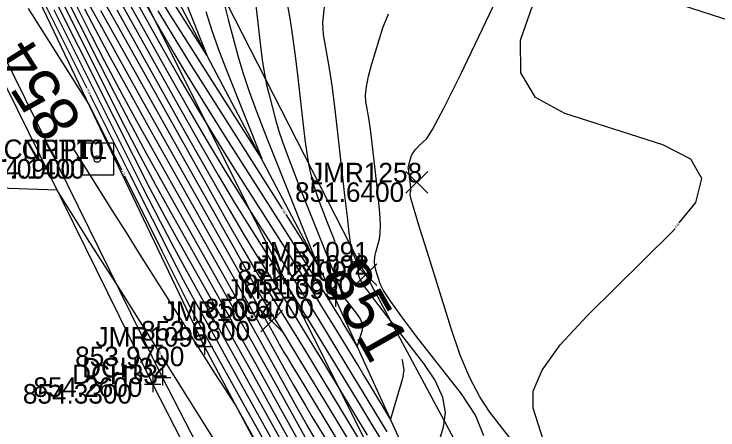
# Model space of a CAD drawing. Extents: x 1654928 to 1810050, y 486881 to 626330.
# Drawn here: x 1801458.38 to 1801501.55, y 489771.84 to 489797.37 of the extents above; entities that cross this region are included whole.
import ezdxf

# ---------------------------------------------------------------- set-up
doc = ezdxf.new("R2010")
doc.units = 0
for name, color, linetype in [('DR_X_Ditch', 7, 'Continuous'), ('DT_X_Contour_Major', 7, 'Continuous'), ('DT_X_Contour_Minor', 7, 'Continuous'), ('PV_X_EOP', 7, 'Continuous'), ('PV_X_Shoulder', 7, 'Continuous'), ('RD_X_Fence', 7, 'Continuous'), ('RW_X_Esmt_SH', 7, 'Continuous'), ('SV_P_Control_Cells_Set', 7, 'Continuous'), ('SV_X_Break_Lines', 7, 'Continuous'), ('SV_X_Control_Cells_Found', 7, 'Continuous'), ('SV_X_Random_Point', 7, 'Continuous'), ('SV_X_Shot_Marker', 7, 'Continuous'), ('SV_X_Text_Elevation', 7, 'Continuous'), ('SV_X_Text_Name', 7, 'Continuous')]:
    doc.layers.add(name, color=color, linetype=linetype)

msp = doc.modelspace()

# ---------------------------------------------------------------- linework, layer by layer
at = {"layer": 'DR_X_Ditch'}
msp.add_lwpolyline([(1801540.062, 489643.432), (1801532.556, 489660.144), (1801517.868, 489690.883), (1801504.345, 489723.544), (1801491.469, 489750.565), (1801478.102, 489779.895), (1801464.666, 489805.356), (1801460.448, 489815.434)], dxfattribs=at)
at = {"layer": 'DT_X_Contour_Major'}
for points in [[(1801511.18, 489796.356), (1801511.157, 489796.211), (1801510.687, 489795.44), (1801509.604, 489795.13), (1801507.907, 489795.282), (1801505.597, 489795.895), (1801498.619, 489798.146), (1801496.431, 489799.099), (1801495.102, 489800.27), (1801494.631, 489801.658), (1801495.019, 489803.265), (1801497.199, 489807.839)], [(1801482.153, 489776.192), (1801482.179, 489776.131), (1801482.279, 489775.543), (1801482.207, 489774.992), (1801481.469, 489772.507), (1801480.075, 489774.807), (1801479.77, 489775.309), (1801479.454, 489775.83), (1801479.127, 489776.37), (1801477.871, 489778.441), (1801477.427, 489779.164), (1801476.781, 489780.197), (1801475.934, 489781.541), (1801474.886, 489783.196), (1801471.824, 489788.021), (1801470.69, 489789.837), (1801469.582, 489791.664), (1801468.501, 489793.504), (1801467.447, 489795.356), (1801464.672, 489800.31)], [(1801492.367, 489742.188), (1801490.238, 489746.399), (1801489.524, 489747.806), (1801488.978, 489748.87), (1801488.601, 489749.591), (1801488.391, 489749.969), (1801484.363, 489756.609), (1801481.276, 489761.695), (1801480.136, 489763.593), (1801479.031, 489765.475), (1801477.96, 489767.339), (1801476.925, 489769.186), (1801474.21, 489774.088), (1801473.207, 489775.896), (1801472.235, 489777.643), (1801471.293, 489779.329), (1801470.381, 489780.954), (1801467.99, 489785.207), (1801467.073, 489786.869), (1801466.115, 489788.665), (1801465.114, 489790.594), (1801464.073, 489792.657), (1801461.24, 489798.336)], [(1801475.156, 489797.899), (1801475.311, 489796.983), (1801475.459, 489795.997), (1801475.6, 489794.941), (1801475.735, 489793.817), (1801476.086, 489790.725), (1801476.212, 489789.67), (1801476.326, 489788.824), (1801476.429, 489788.187), (1801476.52, 489787.758), (1801476.749, 489786.893), (1801476.861, 489786.515), (1801477.027, 489786.03), (1801477.247, 489785.437), (1801477.521, 489784.737), (1801478.05, 489783.412)], [(1801463.673, 489797.598), (1801464.857, 489795.484), (1801468.386, 489789.206), (1801469.596, 489787.053), (1801470.581, 489785.3), (1801471.339, 489783.949), (1801471.872, 489782.999), (1801472.991, 489781.001), (1801473.369, 489780.329), (1801473.663, 489779.81), (1801473.874, 489779.445), (1801474.001, 489779.234), (1801474.227, 489778.877), (1801474.475, 489778.474), (1801475.048, 489777.532), (1801475.947, 489776.053), (1801477.171, 489774.035), (1801480.869, 489767.936), (1801482.228, 489765.694), (1801483.532, 489763.544), (1801484.781, 489761.485), (1801485.974, 489759.517), (1801487.345, 489757.255)], [(1801487.169, 489745.96), (1801486.321, 489747.603), (1801485.711, 489748.755), (1801485.34, 489749.416), (1801484.668, 489750.523), (1801484.219, 489751.3), (1801483.375, 489752.798), (1801482.136, 489755.02), (1801480.504, 489757.963), (1801471.964, 489773.384), (1801471.097, 489774.705), (1801470.917, 489774.981), (1801470.593, 489775.488), (1801470.447, 489775.718), (1801470.076, 489776.314), (1801469.855, 489776.667), (1801469.471, 489777.279), (1801468.213, 489779.28), (1801466.1, 489782.638), (1801465.27, 489783.958), (1801464.364, 489785.399), (1801463.382, 489786.961), (1801461.991, 489789.174)]]:
    msp.add_lwpolyline(points, dxfattribs=at)
at = {"layer": 'DT_X_Contour_Minor'}
for points in [[(1801489.278, 489770.727), (1801487.566, 489772.927), (1801486.936, 489773.868), (1801486.33, 489775.039), (1801485.747, 489776.441), (1801485.189, 489778.073), (1801483.73, 489782.734), (1801483.253, 489784.269), (1801482.917, 489785.38), (1801482.72, 489786.066), (1801482.664, 489786.327), (1801482.7, 489786.457), (1801482.71, 489786.519), (1801482.712, 489786.609), (1801482.706, 489786.726), (1801482.692, 489786.87), (1801482.644, 489787.292), (1801482.627, 489787.437), (1801482.612, 489787.557), (1801482.599, 489787.65), (1801482.588, 489787.718), (1801482.562, 489787.865), (1801482.558, 489787.931), (1801482.568, 489788.017), (1801482.59, 489788.124), (1801482.625, 489788.252), (1801482.735, 489788.622), (1801482.794, 489788.765), (1801482.891, 489788.918), (1801483.023, 489789.082), (1801483.193, 489789.255), (1801483.692, 489789.729), (1801484.047, 489790.283), (1801484.734, 489791.59), (1801485.754, 489793.65), (1801487.107, 489796.463), (1801491.16, 489804.967)], [(1801473.171, 489798.214), (1801473.277, 489797.362), (1801473.521, 489795.207), (1801473.621, 489794.426), (1801473.737, 489793.698), (1801473.87, 489793.023), (1801474.019, 489792.402), (1801474.437, 489790.816), (1801474.643, 489790.123), (1801474.948, 489789.234), (1801475.352, 489788.147), (1801475.854, 489786.864), (1801477.806, 489781.967), (1801478.152, 489781.09), (1801478.361, 489780.549), (1801478.434, 489780.344), (1801478.444, 489780.247), (1801478.473, 489780.181), (1801478.554, 489780.057), (1801478.686, 489779.876), (1801478.869, 489779.636), (1801479.426, 489778.92), (1801479.601, 489778.659), (1801479.708, 489778.413), (1801479.748, 489778.181), (1801479.719, 489777.964), (1801479.429, 489776.985), (1801478.879, 489777.891), (1801478.506, 489778.507), (1801478.373, 489778.727), (1801478.011, 489779.323), (1801477.722, 489779.786), (1801477.127, 489780.73), (1801475.018, 489784.059), (1801471.389, 489789.779), (1801470.091, 489791.846), (1801468.92, 489793.76), (1801467.874, 489795.52), (1801466.955, 489797.126), (1801464.671, 489801.203)], [(1801492.762, 489740.113), (1801488.304, 489748.928), (1801488.056, 489749.367), (1801487.533, 489750.251), (1801486.734, 489751.581), (1801485.66, 489753.356), (1801482.427, 489758.683), (1801481.211, 489760.71), (1801479.988, 489762.798), (1801478.759, 489764.946), (1801477.523, 489767.154), (1801474.218, 489773.122), (1801473.044, 489775.238), (1801472.003, 489777.112), (1801471.093, 489778.742), (1801470.316, 489780.13), (1801468.418, 489783.506), (1801467.641, 489784.923), (1801466.734, 489786.64), (1801465.697, 489788.659), (1801464.53, 489790.979), (1801460.148, 489799.762)], [(1801492.015, 489745.473), (1801490.721, 489748.032), (1801490.228, 489748.984), (1801489.722, 489749.919), (1801489.202, 489750.836), (1801488.668, 489751.737), (1801481.987, 489762.756), (1801479.933, 489766.141), (1801478.189, 489769.015), (1801477.544, 489770.088), (1801476.919, 489771.151), (1801476.314, 489772.205), (1801475.729, 489773.249), (1801474.195, 489776.02), (1801473.533, 489777.211), (1801472.699, 489778.705), (1801471.691, 489780.502), (1801467.135, 489788.61), (1801465.937, 489790.762), (1801464.875, 489792.713), (1801463.948, 489794.463), (1801463.158, 489796.012), (1801461.231, 489799.874)], [(1801492.191, 489743.83), (1801490.479, 489747.216), (1801489.876, 489748.395), (1801489.35, 489749.394), (1801488.901, 489750.214), (1801488.53, 489750.853), (1801487.294, 489752.892), (1801482.148, 489761.375), (1801479.732, 489765.355), (1801478.84, 489766.841), (1801477.975, 489768.313), (1801477.137, 489769.772), (1801476.327, 489771.217), (1801474.202, 489775.054), (1801473.37, 489776.553), (1801472.467, 489778.174), (1801471.492, 489779.916), (1801467.563, 489786.909), (1801466.505, 489788.816), (1801465.495, 489790.689), (1801464.531, 489792.529), (1801463.615, 489794.334), (1801461.235, 489799.105)], [(1801481.27, 489771.723), (1801479.748, 489774.233), (1801479.205, 489775.13), (1801477.731, 489777.56), (1801477.131, 489778.542), (1801476.434, 489779.664), (1801475.642, 489780.928), (1801474.755, 489782.332), (1801472.26, 489786.264), (1801471.288, 489787.827), (1801470.244, 489789.569), (1801469.128, 489791.488), (1801467.939, 489793.586), (1801464.673, 489799.417)], [(1801468.834, 489798.299), (1801470.208, 489794.854), (1801467.323, 489799.402)], [(1801462.866, 489792.795), (1801461.252, 489796.03), (1801459.873, 489798.793)], [(1801462.782, 489798.333), (1801463.635, 489796.762), (1801464.801, 489794.655), (1801466.28, 489792.013), (1801473.162, 489779.767), (1801473.859, 489778.525), (1801474.179, 489777.952), (1801474.533, 489777.312), (1801474.668, 489777.072), (1801474.808, 489776.828), (1801474.952, 489776.583), (1801475.101, 489776.335), (1801475.504, 489775.672), (1801475.798, 489775.186), (1801478.407, 489770.885)], [(1801463.78, 489798.337), (1801464.797, 489796.522), (1801470.032, 489787.175), (1801471.355, 489784.822), (1801472.384, 489783.007), (1801473.121, 489781.73), (1801473.565, 489780.992), (1801474.359, 489779.741), (1801474.767, 489779.087), (1801475.395, 489778.065), (1801476.243, 489776.675), (1801477.311, 489774.916), (1801480.453, 489769.734)], [(1801464.674, 489798.523), (1801468.431, 489791.816), (1801469.754, 489789.473), (1801470.906, 489787.473), (1801471.886, 489785.818), (1801472.695, 489784.506), (1801474.623, 489781.468), (1801475.351, 489780.314), (1801476.088, 489779.131), (1801476.835, 489777.92), (1801477.591, 489776.679), (1801479.621, 489773.331), (1801480.37, 489772.096), (1801481.093, 489770.903)], [(1801470.135, 489797.521), (1801470.5, 489796.367), (1801470.908, 489795.2), (1801471.36, 489794.021), (1801473.567, 489788.488), (1801468.933, 489795.793), (1801468.003, 489797.271), (1801467.199, 489798.576)], [(1801499.179, 489784.546), (1801500.188, 489785.805), (1801500.564, 489787.284), (1801499.89, 489788.462), (1801498.165, 489789.339), (1801492.163, 489791.274), (1801490.36, 489792.258), (1801489.451, 489793.757), (1801489.437, 489795.771), (1801490.318, 489798.3)], [(1801471.311, 489797.86), (1801471.517, 489797.046), (1801472.126, 489794.739), (1801472.407, 489793.779), (1801472.794, 489792.626), (1801473.287, 489791.281), (1801473.885, 489789.744), (1801476.927, 489782.123), (1801475.06, 489785.065)], [(1801477.408, 489797.793), (1801477.305, 489796.843), (1801477.343, 489796.122), (1801477.633, 489794.505), (1801477.75, 489793.786), (1801477.882, 489792.841), (1801478.03, 489791.669), (1801478.193, 489790.272), (1801478.651, 489786.243), (1801478.802, 489784.915), (1801478.915, 489783.95), (1801478.988, 489783.35), (1801479.022, 489783.114), (1801479.06, 489782.97), (1801479.079, 489782.907), (1801479.107, 489782.826), (1801479.143, 489782.727), (1801479.189, 489782.611), (1801479.323, 489782.276), (1801479.368, 489782.147), (1801479.405, 489782.013), (1801479.434, 489781.872), (1801479.453, 489781.725), (1801479.494, 489781.327), (1801479.614, 489781.059), (1801479.943, 489780.555), (1801480.481, 489779.815), (1801481.228, 489778.838), (1801483.5, 489775.919), (1801484.213, 489774.855), (1801484.65, 489773.85), (1801484.811, 489772.905), (1801484.695, 489772.02), (1801483.51, 489768.029)], [(1801467.18, 489776.791), (1801467.009, 489777.063), (1801464.656, 489780.803), (1801463.754, 489782.209), (1801463.541, 489782.543), (1801463.288, 489782.942), (1801462.995, 489783.407), (1801462.662, 489783.936), (1801461.017, 489786.56), (1801458.059, 489786.668), (1801457.409, 489786.828), (1801456.726, 489787.262), (1801456.01, 489787.969), (1801455.261, 489788.95), (1801453.219, 489791.931), (1801452.443, 489792.987), (1801451.645, 489793.918), (1801450.825, 489794.725), (1801449.983, 489795.408), (1801447.709, 489797.063), (1801446.866, 489797.696)], [(1801464.981, 489787.794), (1801462.976, 489791.812), (1801459.274, 489797.704)], [(1801489.315, 489745.633), (1801488.292, 489747.652), (1801487.835, 489748.515), (1801487.23, 489749.589), (1801486.479, 489750.874), (1801485.58, 489752.371), (1801482.987, 489756.643), (1801481.953, 489758.374), (1801480.798, 489760.365), (1801479.52, 489762.614), (1801478.121, 489765.122), (1801474.226, 489772.156), (1801472.882, 489774.581), (1801471.771, 489776.581), (1801470.894, 489778.156), (1801470.251, 489779.305), (1801468.846, 489781.805), (1801468.21, 489782.976), (1801467.354, 489784.616), (1801466.28, 489786.725), (1801464.987, 489789.302), (1801461.248, 489796.798), (1801460.838, 489797.619)], [(1801462.701, 489797.69), (1801463.365, 489796.398), (1801464.255, 489794.738), (1801465.369, 489792.709), (1801466.707, 489790.312), (1801470.577, 489783.428), (1801471.891, 489781.089), (1801473.696, 489777.868), (1801474.187, 489776.986), (1801475.131, 489775.281), (1801475.491, 489774.638), (1801475.864, 489773.99), (1801476.248, 489773.336), (1801476.645, 489772.675), (1801477.718, 489770.906)], [(1801464.675, 489797.63), (1801468.923, 489790.046), (1801470.381, 489787.457), (1801471.568, 489785.378), (1801472.484, 489783.808), (1801473.13, 489782.749), (1801474.491, 489780.604), (1801475.059, 489779.701), (1801475.741, 489778.598), (1801476.539, 489777.297), (1801477.451, 489775.797), (1801480.037, 489771.533)], [(1801474.835, 489785.419), (1801470.543, 489792.184), (1801469.262, 489794.22), (1801468.155, 489796.018), (1801467.222, 489797.576)], [(1801487.192, 489771.477), (1801486.679, 489772.747), (1801485.821, 489774.054), (1801483.071, 489777.587), (1801482.158, 489778.783), (1801481.479, 489779.72), (1801481.035, 489780.399), (1801480.827, 489780.82), (1801480.584, 489781.597), (1801480.514, 489781.888), (1801480.488, 489782.18), (1801480.505, 489782.472), (1801480.565, 489782.764), (1801480.783, 489783.543), (1801480.841, 489783.917), (1801480.852, 489784.455), (1801480.816, 489785.158), (1801480.732, 489786.024), (1801480.444, 489788.553), (1801480.343, 489789.425), (1801480.253, 489790.142), (1801480.176, 489790.704), (1801480.111, 489791.112), (1801479.952, 489791.994), (1801479.932, 489792.387), (1801479.988, 489792.905), (1801480.12, 489793.549), (1801480.33, 489794.317), (1801480.992, 489796.533), (1801481.349, 489797.394)], [(1801490.034, 489742.915), (1801488.28, 489746.377), (1801487.613, 489747.663), (1801486.927, 489748.927), (1801486.223, 489750.168), (1801485.5, 489751.386), (1801483.547, 489754.603), (1801482.696, 489756.038), (1801481.608, 489757.931), (1801480.282, 489760.282), (1801478.719, 489763.09), (1801474.233, 489771.19), (1801472.719, 489773.923), (1801471.539, 489776.05), (1801470.695, 489777.569), (1801470.185, 489778.481), (1801469.273, 489780.103), (1801468.778, 489781.03), (1801467.974, 489782.592), (1801466.863, 489784.79), (1801465.445, 489787.624), (1801463.053, 489792.419)], [(1801488.268, 489745.101), (1801487.391, 489746.811), (1801486.624, 489748.265), (1801485.967, 489749.461), (1801485.42, 489750.401), (1801484.108, 489752.563), (1801483.439, 489753.702), (1801482.418, 489755.498), (1801481.044, 489757.95), (1801479.317, 489761.059), (1801474.241, 489770.224), (1801472.556, 489773.266), (1801471.307, 489775.519), (1801470.496, 489776.982), (1801470.12, 489777.656), (1801469.701, 489778.402), (1801469.444, 489778.887), (1801468.985, 489779.785), (1801468.325, 489781.095), (1801467.464, 489782.816), (1801465.168, 489787.418)], [(1801490.984, 489770.746), (1801490.221, 489773.183), (1801490.215, 489774.225), (1801490.768, 489775.52), (1801491.881, 489777.07), (1801493.554, 489778.874), (1801498.761, 489784.024), (1801498.916, 489784.218)], [(1801486.948, 489745.108), (1801486.018, 489746.941), (1801485.456, 489748.048), (1801485.26, 489748.431), (1801485.228, 489748.483), (1801485.207, 489748.52), (1801485.167, 489748.592), (1801485.108, 489748.697), (1801485.03, 489748.838), (1801484.623, 489749.572), (1801477.981, 489759.704), (1801476.602, 489761.817), (1801475.312, 489763.816), (1801474.111, 489765.7), (1801472.999, 489767.47), (1801470.153, 489772.036), (1801469.156, 489773.634), (1801468.299, 489775.005), (1801467.584, 489776.148), (1801467.404, 489776.435)]]:
    msp.add_lwpolyline(points, dxfattribs=at)
at = {"layer": 'PV_X_EOP'}
msp.add_lwpolyline([(1801533.684, 489642.188), (1801522.484, 489664.508), (1801511.881, 489685.341), (1801500.299, 489708.684), (1801491.104, 489726.659), (1801480.832, 489747.383), (1801466.882, 489774.659), (1801456.506, 489795.715), (1801444.637, 489819.009), (1801433.258, 489841.444), (1801422.029, 489863.995), (1801410.905, 489885.928), (1801399.817, 489908.089), (1801388.576, 489930.656), (1801376.228, 489955.188), (1801366.008, 489975.62), (1801354.725, 489997.894)], dxfattribs=at)
at = {"layer": 'PV_X_Shoulder'}
msp.add_lwpolyline([(1801534.471, 489642.456), (1801522.963, 489664.954), (1801512.6, 489685.485), (1801500.973, 489709.112), (1801491.766, 489727.019), (1801481.526, 489747.768), (1801467.484, 489775.07), (1801457.116, 489796.092), (1801445.57, 489819.398), (1801434.029, 489841.927), (1801422.682, 489864.343), (1801411.885, 489886.25), (1801400.664, 489908.455), (1801366.703, 489976.232), (1801355.676, 489998.276)], dxfattribs=at)
at = {"layer": 'RD_X_Fence'}
msp.add_lwpolyline([(1801551.601, 489647.601), (1801542.924, 489663.468), (1801525.109, 489695.967), (1801509.688, 489725.543), (1801495.067, 489753.216), (1801479.522, 489782.185), (1801467.623, 489805.516), (1801461.848, 489815.569), (1801444.198, 489848.97), (1801434.479, 489868.8), (1801422.196, 489892.762), (1801414.797, 489907.008)], dxfattribs=at)
at = {"layer": 'RW_X_Esmt_SH'}
msp.add_line((1801569.151, 489592.806), (1801345.762, 490039.449), dxfattribs=at)
at = {"layer": 'SV_P_Control_Cells_Set'}
msp.add_lwpolyline([(1801462.492, 489789.461), (1801464.472, 489789.461), (1801464.472, 489787.48), (1801462.492, 489787.48), (1801462.492, 489789.461)], dxfattribs=at)
msp.add_circle((1801463.482, 489788.47), 0.2, dxfattribs=at)
at = {"layer": 'SV_X_Break_Lines'}
msp.add_lwpolyline([(1801537.196, 489641.719), (1801528.364, 489658.964), (1801513.29, 489687.828), (1801498.001, 489720.37), (1801485.256, 489748.381), (1801470.065, 489776.956), (1801457.973, 489802.299), (1801452.712, 489809.925), (1801448.007, 489818.919)], dxfattribs=at)
at = {"layer": 'SV_X_Control_Cells_Found'}
msp.add_lwpolyline([(1801462.492, 489789.462), (1801464.472, 489789.462), (1801464.472, 489787.48), (1801462.492, 489787.48), (1801462.492, 489789.462)], dxfattribs=at)
msp.add_circle((1801463.482, 489788.47), 0.2, dxfattribs=at)
at = {"layer": 'SV_X_Random_Point'}
for p, q in [((1801482.417, 489786.372), (1801483.75, 489787.707)), ((1801482.417, 489787.707), (1801483.75, 489786.372)), ((1801479.288, 489780.702), (1801480.621, 489782.037)), ((1801479.288, 489782.037), (1801480.621, 489780.702)), ((1801473.508, 489777.864), (1801474.841, 489779.199)), ((1801473.508, 489779.199), (1801474.841, 489777.864))]:
    msp.add_line(p, q, dxfattribs=at)
at = {"layer": 'SV_X_Shot_Marker'}
for p, q in [((1801479.522, 489782.685), (1801479.522, 489781.685)), ((1801479.022, 489782.185), (1801480.022, 489782.185)), ((1801479.522, 489782.185), (1801479.522, 489782.185)), ((1801478.102, 489780.395), (1801478.102, 489779.395)), ((1801477.602, 489779.895), (1801478.602, 489779.895)), ((1801478.102, 489779.895), (1801478.102, 489779.895)), ((1801470.065, 489777.456), (1801470.065, 489776.456)), ((1801469.565, 489776.956), (1801470.565, 489776.956)), ((1801470.065, 489776.956), (1801470.065, 489776.956)), ((1801467.484, 489775.57), (1801467.484, 489774.57)), ((1801466.882, 489775.159), (1801466.882, 489774.159)), ((1801466.984, 489775.07), (1801467.984, 489775.07)), ((1801467.484, 489775.07), (1801467.484, 489775.07)), ((1801466.382, 489774.659), (1801467.382, 489774.659)), ((1801466.882, 489774.659), (1801466.882, 489774.659))]:
    msp.add_line(p, q, dxfattribs=at)

# ---------------------------------------------------------------- texts
at = {"layer": 'DT_X_Contour_Major'}
for s, rotation, p in [('854', 122.271, (1801462.636, 489790.794)), ('851', 299.6071, (1801477.224, 489781.241))]:
    msp.add_text(s, height=2.8, rotation=rotation, dxfattribs=at).set_placement(p)
at = {"layer": 'DT_X_Contour_Minor'}
for s, rotation, p in [('854', 116.5119, (1801463.093, 489792.496)), ('854', 116.5119, (1801465.208, 489787.495)), ('851', 122.3966, (1801475.078, 489785.167)), ('852', 231.2884, (1801499.092, 489784.55)), ('854', 122.1205, (1801467.436, 489776.516))]:
    msp.add_text(s, height=0.14, rotation=rotation, dxfattribs=at).set_placement(p)
at = {"layer": 'SV_X_Text_Elevation'}
for s, p in [('854.0900', (1801455.423, 489787.27)), ('854.1400', (1801456.019, 489787.27)), ('851.6400', (1801475.611, 489785.84)), ('851.2400', (1801472.087, 489780.985)), ('851.3600', (1801472.472, 489780.169)), ('850.6700', (1801470.071, 489778.695)), ('852.0800', (1801466.163, 489777.331)), ('853.9700', (1801462.128, 489775.756)), ('854.2600', (1801459.557, 489773.87)), ('854.3300', (1801458.917, 489773.459))]:
    msp.add_text(s, height=1.2, dxfattribs=at).set_placement(p)
at = {"layer": 'SV_X_Text_Name'}
for s, p in [('CNPT10', (1801457.738, 489788.47)), ('CNPT1', (1801458.843, 489788.47)), ('JMR1258', (1801476.536, 489787.039)), ('JMR1091', (1801473.267, 489782.185)), ('JMR1092', (1801473.275, 489781.369)), ('JMR1093', (1801471.413, 489779.895)), ('JMR1094', (1801467.495, 489778.531)), ('JMR1095', (1801463.376, 489776.956)), ('DCH32', (1801462.552, 489775.07)), ('DCH33', (1801461.941, 489774.659))]:
    msp.add_text(s, height=1.2, dxfattribs=at).set_placement(p)

doc.saveas('drawing.dxf')
